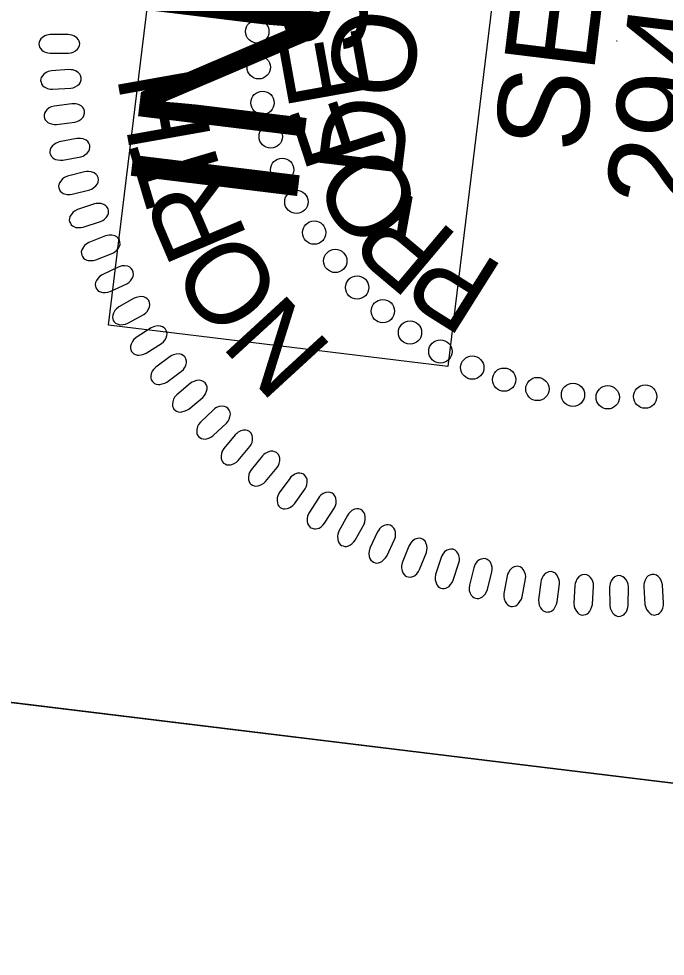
# Model space of a CAD drawing. Extents: x 480344 to 482186, y 488805 to 491553.
# Drawn here: x 480882.7 to 480927.1, y 490365.2 to 490429.6 of the extents above; entities that cross this region are included whole.
import ezdxf

# ---------------------------------------------------------------- set-up
doc = ezdxf.new("R2010")
doc.units = 0
for name, color, linetype in [('Sheet Layout Plan Border', 7, 'Continuous'), ('Sheet PE Seal Cell', 7, 'Continuous'), ('Sheet Plan CELL', 7, 'Continuous'), ('Sheet Sticker Incomplete CELL', 7, 'Continuous')]:
    doc.layers.add(name, color=color, linetype=linetype)

msp = doc.modelspace()

# ---------------------------------------------------------------- linework, layer by layer
at = {"layer": 'Sheet Layout Plan Border'}
msp.add_lwpolyline([(481703.226, 488995.253), (481861.691, 490292.688), (481782.266, 490302.389), (481802.944, 490471.693), (481574.795, 490460.718), (481089.788, 490519.955), (481007.711, 490529.98), (480988.134, 490369.7), (480815.851, 490390.73), (480660.971, 489122.552)], close=True, dxfattribs=at)
at = {"layer": 'Sheet PE Seal Cell'}
msp.add_line((480923.802, 490428.094), (480923.848, 490428.089), dxfattribs=at)
for points in [[(480886.102, 490428.523), (480884.875, 490428.518), (480884.655, 490428.48), (480884.516, 490428.427), (480884.347, 490428.314), (480884.238, 490428.217), (480884.159, 490428.105), (480884.119, 490427.999), (480884.099, 490427.887), (480884.12, 490427.775), (480884.15, 490427.656), (480884.21, 490427.552), (480884.31, 490427.447), (480884.391, 490427.388), (480884.54, 490427.321), (480884.72, 490427.262), (480884.88, 490427.24), (480886.136, 490427.238), (480886.306, 490427.26), (480886.445, 490427.306), (480886.605, 490427.396), (480886.744, 490427.509), (480886.823, 490427.606), (480886.883, 490427.763), (480886.902, 490427.913), (480886.861, 490428.062), (480886.811, 490428.167), (480886.711, 490428.294), (480886.541, 490428.412), (480886.361, 490428.479), (480886.231, 490428.508)], [(480886.178, 490426.115), (480884.955, 490426.033), (480884.738, 490425.981), (480884.602, 490425.92), (480884.44, 490425.796), (480884.338, 490425.693), (480884.265, 490425.575), (480884.233, 490425.468), (480884.22, 490425.355), (480884.247, 490425.244), (480884.285, 490425.127), (480884.352, 490425.027), (480884.458, 490424.928), (480884.542, 490424.874), (480884.696, 490424.817), (480884.879, 490424.77), (480885.039, 490424.758), (480886.294, 490424.834), (480886.461, 490424.868), (480886.598, 490424.921), (480886.751, 490425.022), (480886.883, 490425.143), (480886.956, 490425.245), (480887.005, 490425.406), (480887.015, 490425.556), (480886.965, 490425.703), (480886.909, 490425.804), (480886.801, 490425.924), (480886.624, 490426.032), (480886.44, 490426.087), (480886.309, 490426.108)], [(480886.368, 490423.769), (480885.151, 490423.611), (480884.939, 490423.546), (480884.806, 490423.476), (480884.653, 490423.342), (480884.557, 490423.232), (480884.492, 490423.111), (480884.465, 490423.001), (480884.461, 490422.888), (480884.494, 490422.779), (480884.54, 490422.664), (480884.613, 490422.568), (480884.725, 490422.477), (480884.812, 490422.428), (480884.969, 490422.381), (480885.155, 490422.345), (480885.316, 490422.343), (480886.563, 490422.498), (480886.728, 490422.542), (480886.861, 490422.605), (480887.007, 490422.714), (480887.132, 490422.844), (480887.198, 490422.95), (480887.238, 490423.114), (480887.238, 490423.264), (480887.179, 490423.408), (480887.116, 490423.505), (480887, 490423.618), (480886.817, 490423.714), (480886.63, 490423.758), (480886.498, 490423.771)], [(480886.701, 490421.378), (480885.497, 490421.143), (480885.288, 490421.065), (480885.161, 490420.987), (480885.016, 490420.844), (480884.927, 490420.728), (480884.87, 490420.603), (480884.851, 490420.492), (480884.853, 490420.378), (480884.893, 490420.272), (480884.946, 490420.161), (480885.024, 490420.069), (480885.142, 490419.985), (480885.233, 490419.942), (480885.392, 490419.904), (480885.58, 490419.88), (480885.741, 490419.888), (480886.976, 490420.121), (480887.138, 490420.176), (480887.266, 490420.247), (480887.406, 490420.365), (480887.521, 490420.502), (480887.581, 490420.612), (480887.61, 490420.778), (480887.601, 490420.928), (480887.533, 490421.068), (480887.464, 490421.161), (480887.342, 490421.266), (480887.153, 490421.351), (480886.964, 490421.383), (480886.83, 490421.388)], [(480887.244, 490419.094), (480886.057, 490418.784), (480885.854, 490418.693), (480885.732, 490418.607), (480885.596, 490418.456), (480885.515, 490418.334), (480885.466, 490418.206), (480885.454, 490418.094), (480885.463, 490417.981), (480885.511, 490417.877), (480885.57, 490417.769), (480885.654, 490417.683), (480885.777, 490417.606), (480885.869, 490417.569), (480886.031, 490417.541), (480886.22, 490417.529), (480886.379, 490417.547), (480887.598, 490417.858), (480887.756, 490417.922), (480887.879, 490418.001), (480888.012, 490418.128), (480888.118, 490418.271), (480888.171, 490418.385), (480888.189, 490418.553), (480888.171, 490418.702), (480888.094, 490418.837), (480888.02, 490418.925), (480887.891, 490419.023), (480887.697, 490419.097), (480887.506, 490419.116), (480887.373, 490419.112)], [(480887.913, 490416.879), (480886.748, 490416.496), (480886.552, 490416.392), (480886.435, 490416.298), (480886.309, 490416.139), (480886.236, 490416.012), (480886.195, 490415.881), (480886.189, 490415.769), (480886.206, 490415.656), (480886.26, 490415.556), (480886.325, 490415.452), (480886.415, 490415.371), (480886.542, 490415.302), (480886.637, 490415.271), (480886.8, 490415.253), (480886.989, 490415.253), (480887.148, 490415.281), (480888.343, 490415.667), (480888.498, 490415.741), (480888.616, 490415.828), (480888.739, 490415.963), (480888.837, 490416.113), (480888.883, 490416.23), (480888.89, 490416.398), (480888.863, 490416.547), (480888.778, 490416.676), (480888.698, 490416.76), (480888.564, 490416.849), (480888.366, 490416.91), (480888.174, 490416.918), (480888.041, 490416.906)], [(480888.668, 490414.689), (480887.528, 490414.232), (480887.338, 490414.116), (480887.228, 490414.016), (480887.112, 490413.849), (480887.047, 490413.718), (480887.014, 490413.584), (480887.016, 490413.472), (480887.04, 490413.361), (480887.099, 490413.264), (480887.172, 490413.164), (480887.266, 490413.089), (480887.398, 490413.029), (480887.494, 490413.003), (480887.658, 490412.996), (480887.847, 490413.007), (480888.003, 490413.046), (480889.173, 490413.506), (480889.322, 490413.59), (480889.435, 490413.684), (480889.549, 490413.826), (480889.638, 490413.982), (480889.675, 490414.102), (480889.673, 490414.27), (480889.636, 490414.416), (480889.543, 490414.54), (480889.458, 490414.619), (480889.318, 490414.7), (480889.116, 490414.747), (480888.924, 490414.743), (480888.793, 490414.723)], [(480889.556, 490412.548), (480888.448, 490412.021), (480888.266, 490411.893), (480888.163, 490411.786), (480888.057, 490411.612), (480888, 490411.477), (480887.976, 490411.342), (480887.985, 490411.23), (480888.015, 490411.12), (480888.081, 490411.027), (480888.16, 490410.932), (480888.258, 490410.863), (480888.393, 490410.812), (480888.491, 490410.792), (480888.655, 490410.795), (480888.843, 490410.819), (480888.997, 490410.866), (480890.135, 490411.399), (480890.279, 490411.492), (480890.386, 490411.593), (480890.491, 490411.742), (480890.569, 490411.903), (480890.6, 490412.025), (480890.586, 490412.193), (480890.54, 490412.336), (480890.44, 490412.454), (480890.35, 490412.528), (480890.205, 490412.6), (480890.001, 490412.635), (480889.809, 490412.618), (480889.68, 490412.59)], [(480890.658, 490410.398), (480889.586, 490409.802), (480889.412, 490409.663), (480889.315, 490409.55), (480889.221, 490409.369), (480889.172, 490409.231), (480889.157, 490409.095), (480889.173, 490408.983), (480889.21, 490408.876), (480889.282, 490408.788), (480889.366, 490408.698), (480889.469, 490408.635), (480889.607, 490408.592), (480889.706, 490408.578), (480889.87, 490408.592), (480890.055, 490408.627), (480890.205, 490408.685), (480891.308, 490409.287), (480891.446, 490409.39), (480891.546, 490409.496), (480891.642, 490409.652), (480891.71, 490409.818), (480891.733, 490409.942), (480891.708, 490410.108), (480891.653, 490410.248), (480891.546, 490410.36), (480891.452, 490410.427), (480891.303, 490410.49), (480891.096, 490410.512), (480890.907, 490410.484), (480890.779, 490410.447)], [(480891.809, 490408.362), (480890.776, 490407.701), (480890.612, 490407.551), (480890.522, 490407.432), (480890.44, 490407.246), (480890.399, 490407.106), (480890.392, 490406.968), (480890.416, 490406.859), (480890.46, 490406.753), (480890.537, 490406.669), (480890.626, 490406.585), (480890.733, 490406.528), (480890.874, 490406.494), (480890.973, 490406.487), (480891.136, 490406.511), (480891.319, 490406.557), (480891.466, 490406.625), (480892.528, 490407.295), (480892.658, 490407.406), (480892.752, 490407.519), (480892.838, 490407.68), (480892.895, 490407.85), (480892.91, 490407.975), (480892.875, 490408.14), (480892.811, 490408.276), (480892.697, 490408.38), (480892.599, 490408.442), (480892.447, 490408.495), (480892.239, 490408.504), (480892.052, 490408.464), (480891.926, 490408.419)], [(480893.12, 490406.401), (480892.13, 490405.677), (480891.975, 490405.517), (480891.893, 490405.392), (480891.823, 490405.201), (480891.792, 490405.059), (480891.794, 490404.921), (480891.823, 490404.813), (480891.873, 490404.71), (480891.956, 490404.632), (480892.051, 490404.553), (480892.161, 490404.504), (480892.303, 490404.478), (480892.403, 490404.477), (480892.563, 490404.511), (480892.743, 490404.569), (480892.885, 490404.645), (480893.904, 490405.382), (480894.027, 490405.5), (480894.113, 490405.618), (480894.189, 490405.785), (480894.236, 490405.959), (480894.243, 490406.084), (480894.198, 490406.246), (480894.125, 490406.378), (480894.005, 490406.475), (480893.903, 490406.53), (480893.748, 490406.574), (480893.541, 490406.571), (480893.356, 490406.518), (480893.233, 490406.466)], [(480894.516, 490404.556), (480893.574, 490403.771), (480893.429, 490403.601), (480893.355, 490403.472), (480893.297, 490403.277), (480893.275, 490403.132), (480893.285, 490402.995), (480893.322, 490402.889), (480893.378, 490402.79), (480893.465, 490402.717), (480893.565, 490402.644), (480893.678, 490402.602), (480893.821, 490402.585), (480893.921, 490402.591), (480894.079, 490402.634), (480894.255, 490402.704), (480894.393, 490402.788), (480895.362, 490403.588), (480895.478, 490403.713), (480895.557, 490403.837), (480895.622, 490404.009), (480895.657, 490404.184), (480895.656, 490404.31), (480895.602, 490404.469), (480895.521, 490404.596), (480895.395, 490404.685), (480895.29, 490404.734), (480895.131, 490404.768), (480894.925, 490404.751), (480894.744, 490404.688), (480894.625, 490404.628)], [(480896.094, 490402.738), (480895.203, 490401.895), (480895.07, 490401.717), (480895.004, 490401.583), (480894.958, 490401.385), (480894.945, 490401.239), (480894.964, 490401.103), (480895.007, 490401), (480895.07, 490400.904), (480895.161, 490400.836), (480895.265, 490400.771), (480895.38, 490400.735), (480895.525, 490400.728), (480895.624, 490400.739), (480895.779, 490400.793), (480895.951, 490400.873), (480896.082, 490400.966), (480896.999, 490401.825), (480897.107, 490401.958), (480897.178, 490402.086), (480897.232, 490402.261), (480897.256, 490402.438), (480897.247, 490402.564), (480897.183, 490402.719), (480897.095, 490402.841), (480896.963, 490402.922), (480896.855, 490402.964), (480896.695, 490402.988), (480896.49, 490402.958), (480896.313, 490402.884), (480896.199, 490402.816)], [(480897.599, 490401.018), (480896.813, 490400.077), (480896.701, 490399.884), (480896.652, 490399.743), (480896.629, 490399.541), (480896.634, 490399.395), (480896.669, 490399.262), (480896.724, 490399.165), (480896.797, 490399.077), (480896.896, 490399.02), (480897.007, 490398.967), (480897.125, 490398.945), (480897.27, 490398.955), (480897.367, 490398.978), (480897.514, 490399.05), (480897.676, 490399.15), (480897.795, 490399.258), (480898.605, 490400.218), (480898.697, 490400.362), (480898.752, 490400.498), (480898.785, 490400.679), (480898.788, 490400.857), (480898.764, 490400.981), (480898.682, 490401.127), (480898.581, 490401.238), (480898.44, 490401.304), (480898.328, 490401.332), (480898.166, 490401.337), (480897.966, 490401.284), (480897.799, 490401.189), (480897.693, 490401.108)], [(480899.459, 490399.568), (480898.681, 490398.62), (480898.571, 490398.427), (480898.523, 490398.286), (480898.501, 490398.083), (480898.507, 490397.936), (480898.543, 490397.804), (480898.599, 490397.707), (480898.673, 490397.62), (480898.773, 490397.564), (480898.884, 490397.512), (480899.003, 490397.491), (480899.147, 490397.502), (480899.244, 490397.525), (480899.391, 490397.599), (480899.551, 490397.699), (480899.669, 490397.809), (480900.472, 490398.775), (480900.562, 490398.921), (480900.617, 490399.057), (480900.648, 490399.237), (480900.65, 490399.416), (480900.626, 490399.539), (480900.542, 490399.685), (480900.439, 490399.795), (480900.299, 490399.859), (480900.186, 490399.887), (480900.024, 490399.891), (480899.825, 490399.836), (480899.659, 490399.74), (480899.553, 490399.659)], [(480901.336, 490398.025), (480900.618, 490397.03), (480900.52, 490396.831), (480900.481, 490396.686), (480900.473, 490396.483), (480900.488, 490396.337), (480900.531, 490396.207), (480900.593, 490396.114), (480900.673, 490396.032), (480900.775, 490395.983), (480900.89, 490395.937), (480901.01, 490395.924), (480901.153, 490395.944), (480901.248, 490395.974), (480901.39, 490396.056), (480901.544, 490396.166), (480901.655, 490396.283), (480902.396, 490397.298), (480902.477, 490397.448), (480902.522, 490397.588), (480902.542, 490397.77), (480902.533, 490397.949), (480902.501, 490398.071), (480902.409, 490398.211), (480902.299, 490398.314), (480902.154, 490398.369), (480902.041, 490398.39), (480901.879, 490398.384), (480901.683, 490398.316), (480901.524, 490398.21), (480901.423, 490398.122)], [(480903.309, 490396.667), (480902.656, 490395.629), (480902.57, 490395.424), (480902.54, 490395.277), (480902.545, 490395.074), (480902.569, 490394.929), (480902.621, 490394.802), (480902.689, 490394.713), (480902.773, 490394.636), (480902.878, 490394.593), (480902.996, 490394.555), (480903.116, 490394.55), (480903.257, 490394.579), (480903.351, 490394.614), (480903.487, 490394.705), (480903.634, 490394.825), (480903.738, 490394.948), (480904.414, 490396.008), (480904.484, 490396.163), (480904.52, 490396.305), (480904.53, 490396.488), (480904.509, 490396.666), (480904.47, 490396.785), (480904.369, 490396.92), (480904.253, 490397.016), (480904.105, 490397.062), (480903.99, 490397.075), (480903.829, 490397.059), (480903.638, 490396.979), (480903.486, 490396.863), (480903.391, 490396.769)], [(480905.298, 490395.478), (480904.712, 490394.401), (480904.64, 490394.19), (480904.618, 490394.043), (480904.636, 490393.84), (480904.669, 490393.697), (480904.729, 490393.574), (480904.803, 490393.489), (480904.891, 490393.417), (480904.999, 490393.382), (480905.119, 490393.351), (480905.239, 490393.352), (480905.378, 490393.39), (480905.469, 490393.432), (480905.6, 490393.531), (480905.738, 490393.66), (480905.834, 490393.789), (480906.442, 490394.889), (480906.503, 490395.049), (480906.531, 490395.193), (480906.528, 490395.376), (480906.497, 490395.552), (480906.449, 490395.669), (480906.34, 490395.797), (480906.219, 490395.885), (480906.069, 490395.922), (480905.952, 490395.928), (480905.793, 490395.902), (480905.607, 490395.81), (480905.462, 490395.684), (480905.374, 490395.584)], [(480907.365, 490394.343), (480906.848, 490393.231), (480906.789, 490393.017), (480906.777, 490392.868), (480906.807, 490392.667), (480906.849, 490392.526), (480906.917, 490392.407), (480906.994, 490392.327), (480907.088, 490392.261), (480907.198, 490392.232), (480907.319, 490392.208), (480907.439, 490392.218), (480907.576, 490392.264), (480907.664, 490392.312), (480907.789, 490392.419), (480907.918, 490392.556), (480908.006, 490392.691), (480908.544, 490393.827), (480908.595, 490393.991), (480908.613, 490394.136), (480908.599, 490394.319), (480908.556, 490394.492), (480908.502, 490394.606), (480908.386, 490394.727), (480908.258, 490394.808), (480908.105, 490394.834), (480907.99, 490394.833), (480907.832, 490394.797), (480907.653, 490394.694), (480907.516, 490394.559), (480907.434, 490394.454)], [(480909.519, 490393.371), (480909.072, 490392.228), (480909.027, 490392.011), (480909.024, 490391.861), (480909.067, 490391.662), (480909.117, 490391.525), (480909.192, 490391.409), (480909.276, 490391.334), (480909.373, 490391.275), (480909.484, 490391.252), (480909.607, 490391.237), (480909.726, 490391.254), (480909.86, 490391.309), (480909.945, 490391.361), (480910.062, 490391.477), (480910.183, 490391.622), (480910.262, 490391.762), (480910.727, 490392.93), (480910.768, 490393.096), (480910.777, 490393.242), (480910.751, 490393.423), (480910.699, 490393.594), (480910.637, 490393.704), (480910.512, 490393.817), (480910.38, 490393.89), (480910.227, 490393.907), (480910.111, 490393.899), (480909.956, 490393.852), (480909.784, 490393.738), (480909.655, 490393.596), (480909.58, 490393.485)], [(480911.736, 490392.585), (480911.361, 490391.417), (480911.33, 490391.197), (480911.336, 490391.047), (480911.392, 490390.851), (480911.451, 490390.717), (480911.534, 490390.607), (480911.621, 490390.538), (480911.721, 490390.484), (480911.834, 490390.469), (480911.957, 490390.461), (480912.075, 490390.486), (480912.205, 490390.549), (480912.286, 490390.607), (480912.397, 490390.728), (480912.508, 490390.881), (480912.578, 490391.026), (480912.97, 490392.221), (480912.999, 490392.389), (480912.999, 490392.536), (480912.963, 490392.715), (480912.899, 490392.882), (480912.83, 490392.988), (480912.699, 490393.093), (480912.563, 490393.158), (480912.408, 490393.165), (480912.293, 490393.149), (480912.142, 490393.093), (480911.976, 490392.969), (480911.857, 490392.818), (480911.789, 490392.703)], [(480913.982, 490391.887), (480913.682, 490390.698), (480913.664, 490390.476), (480913.68, 490390.327), (480913.748, 490390.136), (480913.815, 490390.005), (480913.904, 490389.901), (480913.996, 490389.836), (480914.1, 490389.789), (480914.213, 490389.782), (480914.337, 490389.781), (480914.453, 490389.813), (480914.578, 490389.885), (480914.656, 490389.948), (480914.758, 490390.076), (480914.86, 490390.235), (480914.921, 490390.385), (480915.236, 490391.601), (480915.255, 490391.771), (480915.246, 490391.917), (480915.199, 490392.093), (480915.124, 490392.257), (480915.049, 490392.358), (480914.912, 490392.454), (480914.771, 490392.511), (480914.617, 490392.508), (480914.503, 490392.485), (480914.355, 490392.42), (480914.198, 490392.285), (480914.089, 490392.127), (480914.028, 490392.009)], [(480916.274, 490391.319), (480916.049, 490390.113), (480916.045, 490389.89), (480916.071, 490389.743), (480916.15, 490389.556), (480916.225, 490389.43), (480916.321, 490389.331), (480916.416, 490389.273), (480916.523, 490389.232), (480916.637, 490389.232), (480916.76, 490389.239), (480916.874, 490389.278), (480916.995, 490389.357), (480917.068, 490389.425), (480917.162, 490389.559), (480917.254, 490389.725), (480917.305, 490389.878), (480917.544, 490391.112), (480917.553, 490391.282), (480917.534, 490391.428), (480917.475, 490391.601), (480917.391, 490391.759), (480917.31, 490391.855), (480917.166, 490391.943), (480917.023, 490391.99), (480916.869, 490391.978), (480916.756, 490391.948), (480916.613, 490391.874), (480916.465, 490391.729), (480916.365, 490391.565), (480916.313, 490391.443)], [(480918.592, 490390.904), (480918.443, 490389.687), (480918.454, 490389.465), (480918.488, 490389.319), (480918.579, 490389.138), (480918.662, 490389.016), (480918.764, 490388.924), (480918.862, 490388.872), (480918.972, 490388.838), (480919.085, 490388.845), (480919.207, 490388.86), (480919.318, 490388.906), (480919.435, 490388.993), (480919.504, 490389.064), (480919.589, 490389.205), (480919.67, 490389.376), (480919.711, 490389.531), (480919.872, 490390.778), (480919.87, 490390.948), (480919.842, 490391.093), (480919.772, 490391.262), (480919.678, 490391.414), (480919.592, 490391.505), (480919.443, 490391.584), (480919.297, 490391.622), (480919.144, 490391.6), (480919.034, 490391.563), (480918.895, 490391.48), (480918.756, 490391.326), (480918.668, 490391.156), (480918.622, 490391.031)], [(480920.938, 490390.671), (480920.866, 490389.446), (480920.89, 490389.225), (480920.934, 490389.082), (480921.036, 490388.906), (480921.127, 490388.79), (480921.234, 490388.704), (480921.336, 490388.659), (480921.447, 490388.632), (480921.56, 490388.646), (480921.681, 490388.669), (480921.789, 490388.722), (480921.899, 490388.816), (480921.964, 490388.892), (480922.04, 490389.037), (480922.11, 490389.213), (480922.142, 490389.37), (480922.223, 490390.624), (480922.211, 490390.795), (480922.174, 490390.937), (480922.094, 490391.102), (480921.991, 490391.247), (480921.899, 490391.333), (480921.745, 490391.402), (480921.597, 490391.431), (480921.445, 490391.4), (480921.338, 490391.356), (480921.205, 490391.264), (480921.076, 490391.102), (480920.998, 490390.926), (480920.961, 490390.799)], [(480923.322, 490390.545), (480923.326, 490389.319), (480923.365, 490389.1), (480923.417, 490388.96), (480923.53, 490388.791), (480923.628, 490388.681), (480923.74, 490388.602), (480923.845, 490388.563), (480923.958, 490388.543), (480924.069, 490388.564), (480924.189, 490388.594), (480924.294, 490388.654), (480924.397, 490388.755), (480924.457, 490388.835), (480924.524, 490388.984), (480924.583, 490389.164), (480924.605, 490389.323), (480924.608, 490390.58), (480924.585, 490390.749), (480924.539, 490390.889), (480924.449, 490391.048), (480924.337, 490391.187), (480924.239, 490391.267), (480924.081, 490391.326), (480923.932, 490391.345), (480923.782, 490391.305), (480923.678, 490391.255), (480923.551, 490391.155), (480923.433, 490390.985), (480923.366, 490390.805), (480923.337, 490390.675)], [(480925.671, 490390.594), (480925.752, 490389.37), (480925.804, 490389.154), (480925.865, 490389.018), (480925.989, 490388.856), (480926.093, 490388.753), (480926.21, 490388.681), (480926.317, 490388.648), (480926.43, 490388.636), (480926.541, 490388.663), (480926.658, 490388.701), (480926.759, 490388.767), (480926.856, 490388.874), (480926.911, 490388.958), (480926.968, 490389.112), (480927.016, 490389.295), (480927.028, 490389.455), (480926.951, 490390.71), (480926.917, 490390.877), (480926.864, 490391.014), (480926.764, 490391.166), (480926.642, 490391.299), (480926.54, 490391.372), (480926.38, 490391.421), (480926.228, 490391.431), (480926.082, 490391.381), (480925.981, 490391.325), (480925.861, 490391.217), (480925.753, 490391.04), (480925.698, 490390.855), (480925.677, 490390.725)]]:
    msp.add_lwpolyline(points, close=True, dxfattribs=at)
for centre in [(480899.107, 490428.73), (480899.207, 490426.271), (480899.47, 490423.832), (480900.029, 490421.517), (480900.819, 490419.23), (480901.793, 490417.025), (480903.019, 490414.909), (480904.467, 490412.967), (480905.968, 490411.139), (480907.737, 490409.518), (480909.603, 490408.046), (480911.692, 490406.748), (480913.883, 490405.637), (480916.07, 490404.808), (480918.359, 490404.166), (480920.804, 490403.77), (480925.765, 490403.644), (480923.191, 490403.598)]:
    msp.add_circle(centre, 0.801, dxfattribs=at)
at = {"layer": 'Sheet Plan CELL'}
msp.add_line((480815.851, 490390.73), (480964.808, 490372.549), dxfattribs=at)
msp.add_lwpolyline([(480853.149, 490386.174), (480865.278, 490485.486), (480976.961, 490471.846), (480964.808, 490372.549)], close=True, dxfattribs=at)
at = {"layer": 'Sheet Sticker Incomplete CELL'}
msp.add_lwpolyline([(480912.202, 490405.709), (480888.876, 490408.558), (480906.698, 490554.474), (480930.024, 490551.625)], close=True, dxfattribs=at)

# ---------------------------------------------------------------- texts
at = {"layer": 'Sheet PE Seal Cell'}
for s, height, rotation, p in [('SEAL', 6.2363, 83.01787, (480921.543, 490420.268)), ('29470', 6.2363, 83.01787, (480929.202, 490416.34)), ('S', 5.669, 84.32554, (480906.358, 490427.043)), ('E', 5.669, 100.20514, (480906.975, 490424.18)), ('H', 5.669, 100.09226, (480895.975, 490421.296)), ('F', 5.669, 108.14494, (480908.091, 490420.628)), ('T', 5.669, 106.58162, (480896.99, 490417.969)), ('O', 5.669, 124.02453, (480910.759, 490416.578)), ('R', 5.669, 113.07097, (480898.504, 490414.54)), ('R', 5.669, 139.90413, (480913.078, 490414.568)), ('O', 5.669, 126.04969, (480901.088, 490410.723)), ('P', 5.669, 147.84392, (480916.211, 490412.486)), ('N', 5.669, 132.53904, (480904.41, 490406.945))]:
    msp.add_text(s, height=height, rotation=rotation, dxfattribs=at).set_placement(p)
at = {"layer": 'Sheet Sticker Incomplete CELL'}
for s, height, p in [('INCOMPLETE PLANS', 11.52, (480901.674, 490416.012)), ('DO NOT USE FOR R/W ACQUISITION', 5.76, (480908.967, 490418.395))]:
    msp.add_text(s, height=height, rotation=83.03651, dxfattribs=at).set_placement(p)

doc.saveas('drawing.dxf')
